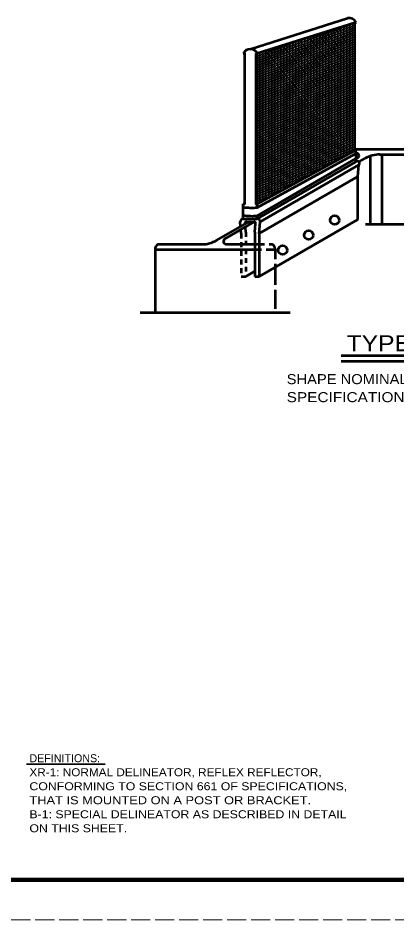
# Model space of a CAD drawing. Extents: x -60 to 620, y -42 to 398.
# Drawn here: x 340.7 to 435.5, y -41.8 to 183.6 of the extents above; entities that cross this region are included whole.
import ezdxf
from ezdxf.enums import TextEntityAlignment as Align

# ---------------------------------------------------------------- set-up
doc = ezdxf.new("R2010")
doc.units = 0
doc.header["$LTSCALE"] = 0.8
for name, pattern in [('LONG_DASHED', [7.5, 6, -1.5]), ('MEDIUM_DASHED', [4.5, 3, -1.5]), ('SHORT_DASHED', [2.7, 1.5, -1.2])]:
    doc.linetypes.add(name, pattern=pattern)
doc.layers.add('1', color=7, linetype='Continuous', lineweight=35)
doc.layers.add('61', color=7, linetype='Continuous', lineweight=35)

msp = doc.modelspace()

# ---------------------------------------------------------------- linework, layer by layer
at = {"layer": '1', "lineweight": 53}
for p, q in [((398.7721, 175.8499), (423.1248, 183.5449)), ((424.8831, 182.4024), (425.2407, 182.5154)), ((424.8831, 150.8207), (444.3847, 150.8207)), ((424.8831, 150.5275), (425.2122, 150.7074)), ((425.2122, 149.7751), (425.2122, 150.7074)), ((425.2122, 148.4604), (425.8616, 148.8353)), ((428.7279, 149.0867), (428.7279, 132.0707)), ((431.2068, 149.5082), (443.4472, 149.5082)), ((431.6347, 149.5082), (431.6347, 132.0707)), ((400.5304, 133.4574), (425.2122, 147.7074)), ((401.2776, 132.6421), (425.9593, 146.8921)), ((425.2122, 147.7074), (425.2122, 148.4604)), ((425.9496, 147.6332), (427.4568, 148.5033)), ((401.0221, 129.7217), (425.7038, 143.9717)), ((397.0137, 136.3482), (397.0137, 137.2074)), ((397.0137, 134.3324), (397.0137, 136.3482)), ((397.0399, 134.3273), (397.0184, 136.3475)), ((400.5304, 136.2751), (400.5304, 137.2074)), ((397.0137, 133.4574), (397.0137, 134.3324)), ((397.0399, 134.3273), (397.0137, 134.3324)), ((397.0137, 133.4574), (400.5304, 133.4574)), ((400.5304, 133.4574), (400.5304, 134.2104)), ((401.0221, 119.0342), (425.7038, 133.2842)), ((390.3986, 128.0731), (398.4256, 132.7074)), ((392.4469, 128.4677), (399.7902, 132.7074)), ((396.3649, 131.5178), (396.2666, 132.6421)), ((397.8279, 132.7074), (399.7163, 132.7074)), ((399.8971, 130.0967), (400.0898, 132.2997)), ((401.0221, 129.7217), (401.2776, 132.6421)), ((427.6029, 132.0707), (448.8847, 132.0707)), ((399.8971, 130.0967), (399.8971, 119.0342)), ((401.0221, 129.7217), (401.0221, 119.0342)), ((375.7207, 127.0682), (386.6486, 127.0682)), ((392.8219, 127.0682), (399.8971, 127.0682)), ((374.9707, 125.7557), (374.9707, 110.0057)), ((374.9707, 125.7557), (399.1582, 125.7557)), ((397.6471, 119.0342), (399.8971, 120.3332)), ((396.5221, 119.0342), (397.6471, 119.0342)), ((399.8971, 119.0342), (401.0221, 119.0342)), ((371.2207, 110.0057), (408.7207, 110.0057)), ((421.4774, 99.2887), (493.4133, 99.2887)), ((421.4774, 97.8201), (493.4133, 97.8201))]:
    msp.add_line(p, q, dxfattribs=at)
at = {"layer": '1', "lineweight": 13}
for p, q in [((424.8831, 172.4068), (418.2536, 180.3076)), ((418.3328, 146.9447), (418.3328, 180.3327)), ((424.8831, 172.9903), (418.6406, 180.4299)), ((418.7078, 147.1498), (418.7078, 180.4512)), ((424.8831, 173.5737), (419.0275, 180.5522)), ((419.0828, 147.3549), (419.0828, 180.5697)), ((424.8831, 174.157), (419.4144, 180.6744)), ((419.4578, 147.56), (419.4578, 180.6882)), ((424.8831, 174.7404), (419.8013, 180.7967)), ((419.8328, 147.7652), (419.8328, 180.8067)), ((424.8831, 175.3238), (420.1883, 180.9189)), ((420.2078, 147.9702), (420.2078, 180.9252)), ((424.8831, 175.9072), (420.5752, 181.0412)), ((420.5828, 148.1754), (420.5828, 181.0436)), ((420.9578, 148.3805), (420.9578, 181.1621)), ((424.8831, 176.4907), (420.9622, 181.1634)), ((421.3328, 148.5856), (421.3328, 181.2806)), ((424.8831, 177.074), (421.3491, 181.2857)), ((421.7078, 148.7907), (421.7078, 181.3991)), ((424.8831, 177.6574), (421.7361, 181.4079)), ((422.0828, 148.9958), (422.0828, 181.5176)), ((424.8831, 178.2408), (422.1229, 181.5302)), ((422.4578, 149.2009), (422.4578, 181.6361)), ((424.8831, 178.8242), (422.5098, 181.6525)), ((422.8328, 149.406), (422.8328, 181.7546)), ((424.8831, 179.4076), (422.8968, 181.7747)), ((423.2078, 149.6112), (423.2078, 181.873)), ((424.8831, 179.991), (423.2837, 181.897)), ((423.5828, 149.8162), (423.5828, 181.9915)), ((424.8831, 180.5744), (423.6707, 182.0192)), ((423.9578, 150.0214), (423.9578, 182.11)), ((424.8831, 181.1577), (424.0576, 182.1416)), ((424.3328, 150.2265), (424.3328, 182.2285)), ((424.8831, 181.7412), (424.4446, 182.2638)), ((424.7078, 150.4316), (424.7078, 182.347)), ((424.8831, 182.3246), (424.8315, 182.3861)), ((411.2078, 143.0476), (411.2078, 178.0813)), ((424.8831, 161.9057), (411.2887, 178.1068)), ((411.5828, 143.2527), (411.5828, 178.1997)), ((424.8831, 162.4891), (411.6757, 178.2292)), ((411.9578, 143.4578), (411.9578, 178.3183)), ((424.8831, 163.0725), (412.0626, 178.3514)), ((412.3328, 143.6629), (412.3328, 178.4367)), ((424.8831, 163.6559), (412.4496, 178.4737)), ((412.7078, 143.8681), (412.7078, 178.5553)), ((424.8831, 164.2393), (412.8365, 178.5959)), ((413.0828, 144.0732), (413.0828, 178.6737)), ((424.8831, 164.8227), (413.2234, 178.7182)), ((413.4578, 144.2782), (413.4578, 178.7922)), ((424.8831, 165.4061), (413.6103, 178.8404)), ((413.8328, 144.4834), (413.8328, 178.9108)), ((424.8831, 165.9895), (413.9973, 178.9627)), ((414.2078, 144.6885), (414.2078, 179.0292)), ((424.8831, 166.5729), (414.3843, 179.0849)), ((414.5828, 144.8936), (414.5828, 179.1477)), ((424.8831, 167.1562), (414.7712, 179.2072)), ((414.9578, 145.0987), (414.9578, 179.2662)), ((424.8831, 167.7397), (415.1581, 179.3295)), ((415.3328, 145.3038), (415.3328, 179.3847)), ((424.8831, 168.3231), (415.5451, 179.4518)), ((415.7078, 145.5089), (415.7078, 179.5032)), ((424.8831, 168.9064), (415.932, 179.574)), ((416.0828, 145.7141), (416.0828, 179.6217)), ((424.8831, 169.4899), (416.3189, 179.6962)), ((416.4578, 145.9192), (416.4578, 179.7402)), ((424.8831, 170.0733), (416.7058, 179.8185)), ((416.8328, 146.1242), (416.8328, 179.8587)), ((424.8831, 170.6567), (417.0928, 179.9408)), ((417.2078, 146.3294), (417.2078, 179.9772)), ((424.8831, 171.2401), (417.4797, 180.0631)), ((417.5828, 146.5345), (417.5828, 180.0957)), ((424.8831, 171.8234), (417.8667, 180.1853)), ((417.9578, 146.7396), (417.9578, 180.2142)), ((404.0828, 139.1505), (404.0828, 175.8299)), ((424.8831, 151.4046), (404.3238, 175.9061)), ((404.4578, 139.3557), (404.4578, 175.9484)), ((424.8831, 151.9879), (404.7108, 176.0284)), ((404.8328, 139.5607), (404.8328, 176.0669)), ((424.8831, 152.5714), (405.0977, 176.1507)), ((405.2078, 139.7658), (405.2078, 176.1854)), ((424.8831, 153.1548), (405.4847, 176.2729)), ((405.5828, 139.9709), (405.5828, 176.3039)), ((424.8831, 153.7382), (405.8716, 176.3952)), ((405.9578, 140.1761), (405.9578, 176.4224)), ((424.8831, 154.3216), (406.2586, 176.5174)), ((406.3328, 140.3812), (406.3328, 176.5409)), ((424.8831, 154.9049), (406.6455, 176.6397)), ((406.7078, 140.5863), (406.7078, 176.6594)), ((424.8831, 155.4883), (407.0324, 176.7619)), ((407.0828, 140.7914), (407.0828, 176.7779)), ((424.8831, 156.0718), (407.4193, 176.8842)), ((407.4578, 140.9965), (407.4578, 176.8964)), ((424.8831, 156.6552), (407.8063, 177.0064)), ((407.8328, 141.2017), (407.8328, 177.0149)), ((424.8831, 157.2385), (408.1932, 177.1287)), ((408.2078, 141.4067), (408.2078, 177.1334)), ((424.8831, 157.8219), (408.5802, 177.251)), ((408.5828, 141.6118), (408.5828, 177.2518)), ((408.9578, 141.8169), (408.9578, 177.3703)), ((424.8831, 158.4053), (408.9671, 177.3732)), ((409.3328, 142.0221), (409.3328, 177.4888)), ((424.8831, 158.9887), (409.3541, 177.4955)), ((409.7078, 142.2272), (409.7078, 177.6073)), ((424.8831, 159.5722), (409.741, 177.6178)), ((410.0828, 142.4322), (410.0828, 177.7258)), ((424.8831, 160.1555), (410.1279, 177.7401)), ((410.4578, 142.6374), (410.4578, 177.8443)), ((424.8831, 160.7389), (410.5148, 177.8623)), ((410.8328, 142.8425), (410.8328, 177.9628)), ((424.8831, 161.3223), (410.9018, 177.9846)), ((421.6968, 148.7847), (400.1554, 174.4565)), ((421.3612, 148.6011), (400.1554, 173.8732)), ((400.3328, 137.2074), (400.3328, 174.7074)), ((422.0322, 148.9682), (400.4344, 174.7074)), ((400.7078, 137.3045), (400.7078, 174.7635)), ((422.3678, 149.1517), (400.8415, 174.8057)), ((401.0828, 137.5097), (401.0828, 174.882)), ((422.7033, 149.3352), (401.2284, 174.928)), ((401.4578, 137.7147), (401.4578, 175.0005)), ((423.0388, 149.5187), (401.6153, 175.0503)), ((401.8328, 137.9198), (401.8328, 175.119)), ((423.3743, 149.7022), (402.0023, 175.1725)), ((402.2078, 138.1249), (402.2078, 175.2375)), ((423.7099, 149.8858), (402.3892, 175.2947)), ((402.5828, 138.3301), (402.5828, 175.3559)), ((424.0454, 150.0692), (402.7761, 175.4171)), ((402.9578, 138.5352), (402.9578, 175.4744)), ((424.381, 150.2528), (403.1631, 175.5393)), ((403.3328, 138.7403), (403.3328, 175.5929)), ((424.7165, 150.4363), (403.55, 175.6616)), ((403.7078, 138.9454), (403.7078, 175.7114)), ((424.8831, 150.8212), (403.9369, 175.7838)), ((421.0257, 148.4176), (400.1554, 173.2897)), ((420.6901, 148.234), (400.1554, 172.7063)), ((420.3546, 148.0505), (400.1554, 172.1229)), ((420.0191, 147.867), (400.1554, 171.5395)), ((419.6835, 147.6834), (400.1554, 170.9562)), ((419.348, 147.4999), (400.1554, 170.3727)), ((419.0124, 147.3164), (400.1554, 169.7893)), ((418.6769, 147.1329), (400.1554, 169.2059)), ((418.3413, 146.9494), (400.1554, 168.6226)), ((418.0058, 146.7658), (400.1554, 168.0392)), ((417.6703, 146.5823), (400.1554, 167.4557)), ((417.3348, 146.3988), (400.1554, 166.8724)), ((416.9992, 146.2152), (400.1554, 166.2889)), ((416.6637, 146.0317), (400.1554, 165.7056)), ((416.3282, 145.8482), (400.1554, 165.1222)), ((415.9927, 145.6647), (400.1554, 164.5387)), ((415.6571, 145.4812), (400.1554, 163.9554)), ((415.3216, 145.2977), (400.1554, 163.372)), ((414.9861, 145.1142), (400.1554, 162.7886)), ((414.6506, 144.9307), (400.1554, 162.2052)), ((414.315, 144.7471), (400.1554, 161.6218)), ((413.9795, 144.5636), (400.1554, 161.0384)), ((413.6439, 144.38), (400.1554, 160.455)), ((413.3083, 144.1965), (400.1554, 159.8717)), ((412.9728, 144.013), (400.1554, 159.2882)), ((412.6373, 143.8294), (400.1554, 158.7048)), ((412.3018, 143.6459), (400.1554, 158.1214)), ((411.9663, 143.4624), (400.1554, 157.538)), ((411.6307, 143.2789), (400.1554, 156.9547)), ((411.2952, 143.0954), (400.1554, 156.3713)), ((410.9597, 142.9118), (400.1554, 155.7878)), ((410.6241, 142.7283), (400.1554, 155.2044)), ((410.2886, 142.5448), (400.1554, 154.621)), ((409.9531, 142.3612), (400.1554, 154.0377)), ((409.6176, 142.1778), (400.1554, 153.4543)), ((409.282, 141.9942), (400.1554, 152.8708)), ((408.9465, 141.8107), (400.1554, 152.2874)), ((408.6109, 141.6272), (400.1554, 151.7041)), ((408.2754, 141.4437), (400.1554, 151.1207)), ((407.9398, 141.2602), (400.1554, 150.5373)), ((407.6043, 141.0767), (400.1554, 149.9539)), ((407.2688, 140.8931), (400.1554, 149.3704)), ((406.9332, 140.7096), (400.1554, 148.7871)), ((406.5977, 140.526), (400.1554, 148.2037)), ((406.2622, 140.3425), (400.1554, 147.6202)), ((405.9267, 140.159), (400.1554, 147.0369)), ((405.5911, 139.9754), (400.1554, 146.4535)), ((405.2556, 139.7919), (400.1554, 145.8701)), ((404.9201, 139.6084), (400.1554, 145.2867)), ((404.5846, 139.4249), (400.1554, 144.7033)), ((404.249, 139.2414), (400.1554, 144.1199)), ((403.9135, 139.0578), (400.1554, 143.5365)), ((403.5779, 138.8743), (400.1554, 142.9532)), ((403.2424, 138.6908), (400.1554, 142.3697)), ((402.9068, 138.5072), (400.1554, 141.7863)), ((402.5713, 138.3237), (400.1554, 141.2029)), ((402.2358, 138.1402), (400.1554, 140.6195)), ((401.9003, 137.9567), (400.1554, 140.0362)), ((401.5648, 137.7732), (400.1554, 139.4528)), ((401.2292, 137.5897), (400.1554, 138.8693)), ((400.8937, 137.4062), (400.1554, 138.2859)), ((400.5581, 137.2227), (400.1554, 137.7026))]:
    msp.add_line(p, q, dxfattribs=at)
at = {"layer": '1', "linetype": 'SHORT_DASHED', "lineweight": 53}
for p, q in [((396.5221, 129.7217), (396.365, 131.5178)), ((397.6471, 130.0967), (397.4672, 132.1542)), ((396.5221, 129.7217), (396.5221, 119.0342)), ((397.6471, 130.0967), (397.6471, 119.0342))]:
    msp.add_line(p, q, dxfattribs=at)
at = {"layer": '1', "linetype": 'MEDIUM_DASHED', "lineweight": 53}
msp.add_line((399.8971, 127.0682), (404.2207, 127.0682), dxfattribs=at)
at = {"layer": '1', "linetype": 'LONG_DASHED', "lineweight": 53}
msp.add_line((404.9707, 121.7121), (404.9707, 110.0057), dxfattribs=at)
at = {"layer": '1'}
msp.add_line((342.855, -2.8678), (362.5222, -2.8678), dxfattribs=at)
at = {"layer": '1', "lineweight": 53}
msp.add_lwpolyline([(400.1554, 174.7074), (400.1554, 137.2074), (400.5304, 137.2074), (424.8831, 150.5274), (424.8831, 182.4024), (400.5304, 174.7074)], close=True, dxfattribs=at)
for points in [[(397.0137, 137.2074), (397.3887, 137.2074), (397.3887, 174.7074), (397.0137, 174.7074)], [(400.5304, 136.2751), (425.2122, 149.7751), (425.2122, 148.4604), (400.5304, 134.2104)], [(425.7038, 133.2842), (425.7038, 143.9717), (425.9593, 146.8921)]]:
    msp.add_lwpolyline(points, dxfattribs=at)
at = {"layer": '1', "linetype": 'MEDIUM_DASHED', "lineweight": 53}
msp.add_lwpolyline([(399.1582, 125.7557), (404.9707, 125.7557), (404.9707, 121.7121)], dxfattribs=at)
at = {"layer": '1', "lineweight": 53}
for centre in [(419.858, 133.1102), (413.3629, 129.3602), (406.8677, 125.6101)]:
    msp.add_circle(centre, 1.125, dxfattribs=at)
for centre, radius, start, end in [((423.5651, 181.7608), 1.8376, 24.24274, 103.86313), ((398.7721, 173.9257), 1.9243, 23.97063, 156.02937), ((425.3786, 149.1958), 0.6027, 323.26493, 106.02981), ((431.2068, 142.0081), 7.5, 90, 120.00049), ((425.5392, 147.2572), 0.5565, 319.0044, 125.99342), ((399.0575, 150.034), 13.8375, 261.52628, 276.11052), ((397.0137, 132.7074), 0.75, 90, 184.99928), ((399.1588, 145.4218), 11.295, 259.18749, 276.97493), ((400.5304, 132.7074), 0.75, 355.00162, 90), ((397.8279, 132.3324), 0.375, 90, 206.03343), ((399.7162, 132.3324), 0.375, 354.99993, 90), ((392.8219, 127.8182), 0.75, 120, 270), ((376.2603, 125.8893), 1.2966, 114.59713, 185.91311), ((386.6485, 134.5683), 7.5, 270, 300.00003)]:
    msp.add_arc(centre, radius, start, end, dxfattribs=at)
at = {"layer": '1', "linetype": 'MEDIUM_DASHED', "lineweight": 53}
msp.add_arc((403.681, 125.8893), 1.2966, 354.08689, 65.40287, dxfattribs=at)
at = {"layer": '61', "lineweight": 158}
msp.add_line((608.8445, -31.7712), (-30.2155, -31.7512), dxfattribs=at)
at = {"layer": '61', "linetype": 'LONG_DASHED', "lineweight": 13}
msp.add_line((619.7845, -41.7512), (-60.2755, -41.7713), dxfattribs=at)

# ---------------------------------------------------------------- texts
at = {"layer": '1', "width": 1.15}
msp.add_text('TYPE B-1 DELINEATOR', height=4, dxfattribs=at).set_placement((457.07, 100.3326), align=Align.CENTER)
at = {"layer": '1'}
for s, height, width, p in [('SHAPE NOMINAL, PROVIDED MEETS MINIMUM DESIGN', 2.5, 1.1, (407.8817, 92.1167)), ('SPECIFICATIONS AS OUTLINED ON THIS SHEET.', 2.5, 1.15, (407.8817, 87.6167)), ('XR-1: NORMAL DELINEATOR, REFLEX REFLECTOR,', 2, 1.1, (343.5474, -5.8598)), ('CONFORMING TO SECTION 661 OF SPECIFICATIONS,', 2, 1.15, (343.5474, -9.3598)), ('THAT IS MOUNTED ON A POST OR BRACKET.', 2, 1.2, (343.5474, -12.8598)), ('B-1: SPECIAL DELINEATOR AS DESCRIBED IN DETAIL', 2, 1.15, (343.5474, -16.3598)), ('ON THIS SHEET.', 2, 1.15, (343.5474, -19.8598))]:
    msp.add_text(s, height=height, dxfattribs=dict(at, width=width)).set_placement(p)
msp.add_text('DEFINITIONS:', height=2, dxfattribs=at).set_placement((343.5474, -2.3598))

doc.saveas('drawing.dxf')
